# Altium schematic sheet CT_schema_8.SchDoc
size 277 x 170 mm
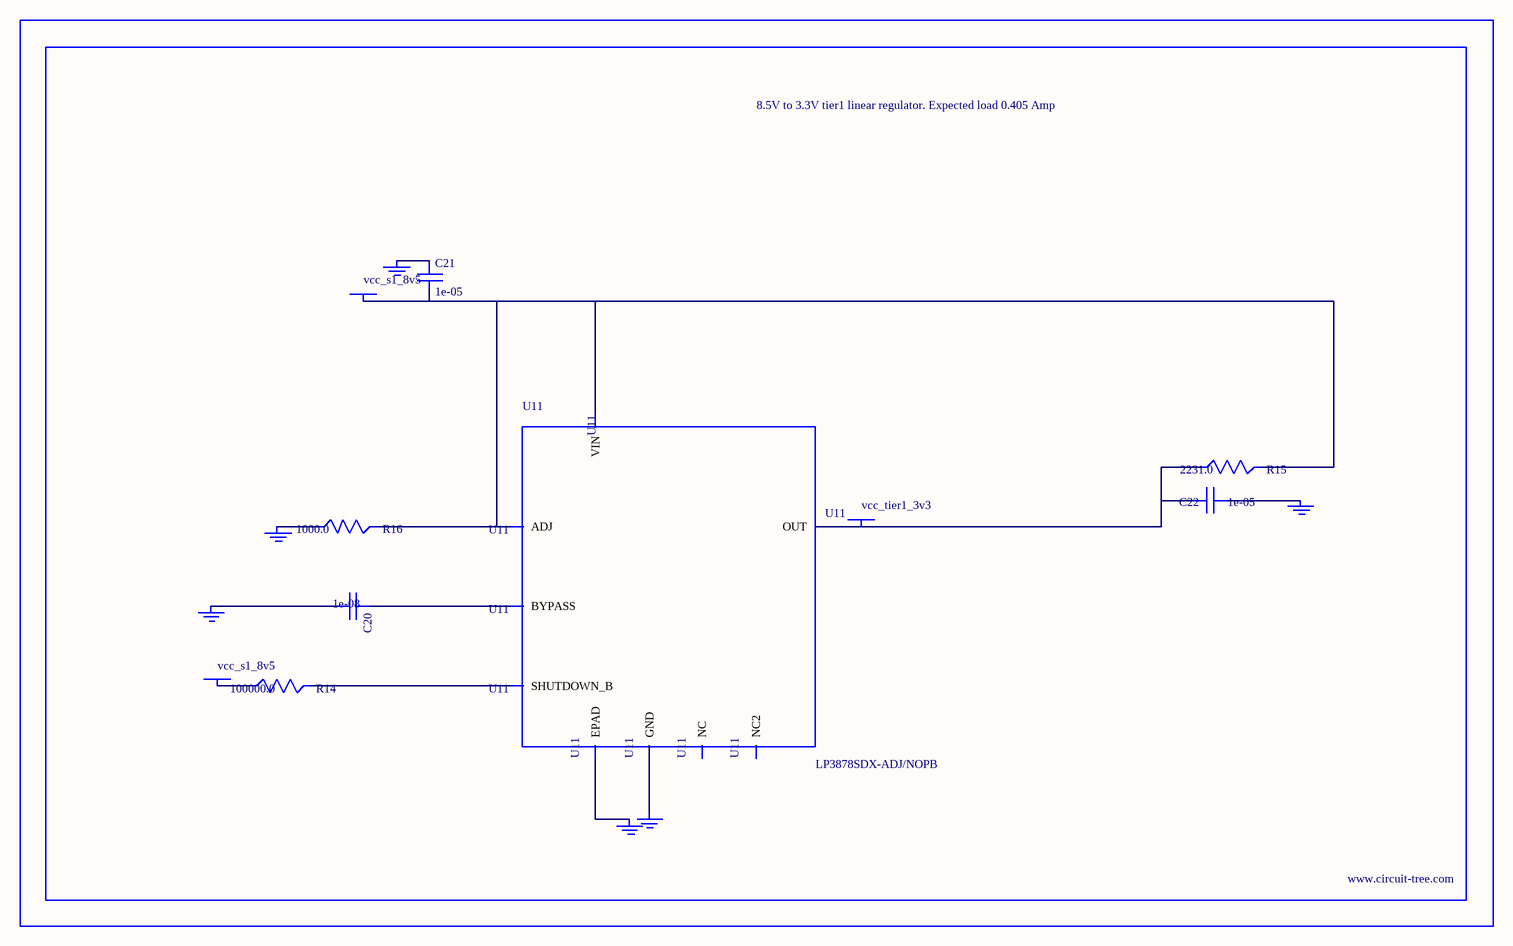
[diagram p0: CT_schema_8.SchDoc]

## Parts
BORDER7  (no value)
C20  1e-08  [C0402]
C21  1e-05  [C1206]
C22  1e-05  [C1210]
GND_INSTANCE_7_0  (no value)
GND_INSTANCE_7_1  (no value)
GND_INSTANCE_7_2  (no value)
GND_INSTANCE_7_3  (no value)
GND_INSTANCE_7_4  (no value)
GND_INSTANCE_7_5  (no value)
POWER_INSTANCE_7_0  vcc_s1_8v5
POWER_INSTANCE_7_1  vcc_s1_8v5
POWER_INSTANCE_7_2  vcc_tier1_3v3
R14  100000.0  [R0603]
R15  2231.0  [R0603]
R16  1000.0  [R0603]
U11  LP3878SDX-ADJ/NOPB  [WSON-8]

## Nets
NetC20_1: C20.1 U11.1(BYPASS)
NetC20_2: C20.2 GND_INSTANCE_7_0.0(GND)
NetC21_1: C21.1 GND_INSTANCE_7_1.0(GND)
NetC21_2: C21.2 POWER_INSTANCE_7_0.0(PWR) R15.2 R16.2 U11.4(VIN) U11.6(ADJ)
NetC22_1: C22.1 GND_INSTANCE_7_2.0(GND)
NetC22_2: C22.2 POWER_INSTANCE_7_2.0(PWR) R15.1 U11.5(OUT)
NetGND_INSTANCE_7_3_0: GND_INSTANCE_7_3.0(GND) R16.1
NetGND_INSTANCE_7_4_0: GND_INSTANCE_7_4.0(GND) U11.PAD(EPAD)
NetGND_INSTANCE_7_5_0: GND_INSTANCE_7_5.0(GND) U11.3(GND)
NetPOWER_INSTANCE_7_1_0: POWER_INSTANCE_7_1.0(PWR) R14.1
NetR14_2: R14.2 U11.8(SHUTDOWN_B)

Not connected (* = marked no-connect by the designer): U11 2(NC) 7(NC2)

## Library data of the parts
BORDER7 = BORDER_PAGE7
C20 = C0402C103K3RAC
C21 = C1206C106K3RACTU
C22 = GRM32DR61E106MA12L
GND_INSTANCE_7_0-GND_INSTANCE_7_5 = GND
POWER_INSTANCE_7_0-POWER_INSTANCE_7_2 = PWR
R14 = RC0603JR-07100KL
R15 = R15
R16 = RC0603JR-071KL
